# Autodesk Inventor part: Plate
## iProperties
Shininess: 20.0
Length Units: 11269
Angle Units: 11279
Time Units: 11290
Mass Units: 11283
Length Display Precision: 3
Angle Display Precision: 2
Created: 2002-01
Part Number: Plate
Document SubType Name: Modeling
Designer: ***
Density: 0.0
Volumn: 0.0
Area: 0.0
PropertySet Name: Model Information
Control State: 0
Master: False
Checked Out: False
Author: ***
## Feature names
1. Extrusion1
